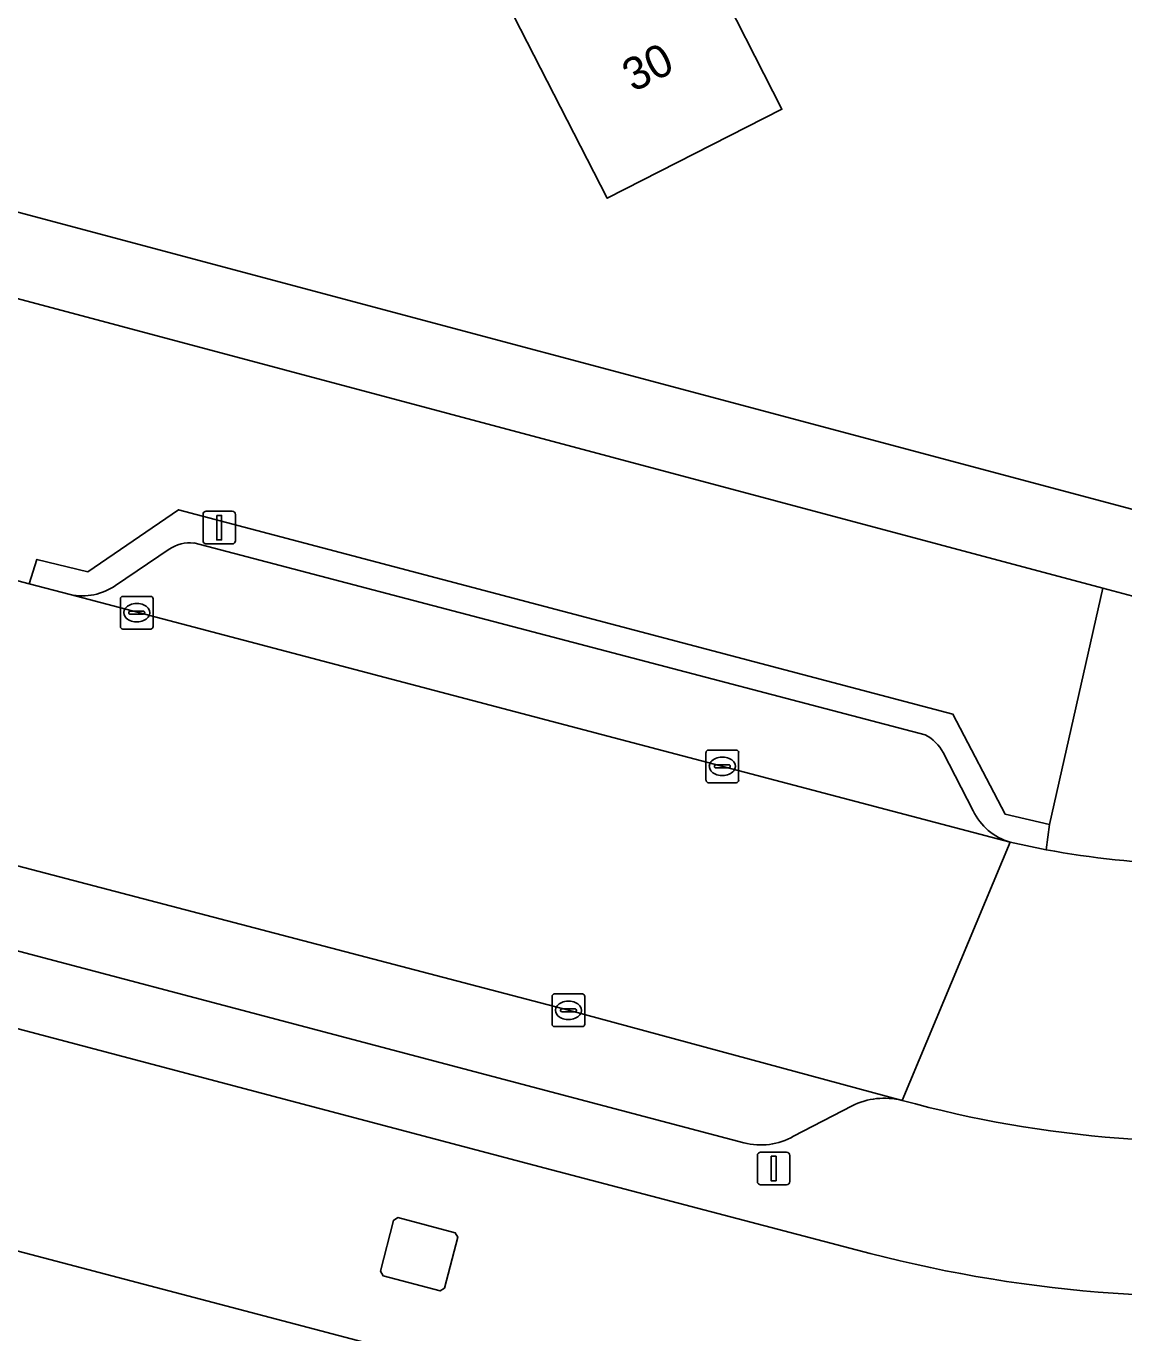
# Model space of a CAD drawing. Extents: x 157692 to 159674, y 381452 to 383291.
# Drawn here: x 158227.96 to 158261.59, y 381802.8 to 381842.84 of the extents above; entities that cross this region are included whole.
import ezdxf

# ---------------------------------------------------------------- set-up
doc = ezdxf.new("R2010")
doc.units = 0
for name, color, linetype in [('IMGEO_Erf', 7, 'Continuous'), ('IMGEO_Groenvoorziening', 7, 'Continuous'), ('IMGEO_Kolk', 7, 'Continuous'), ('IMGEO_Lichtmast', 7, 'Continuous'), ('IMGEO_Pand', 7, 'Continuous'), ('IMGEO_Pand_nummerreeks', 7, 'Continuous'), ('IMGEO_Pand_overbouw', 7, 'Continuous'), ('IMGEO_Parkeervlak_open', 7, 'Continuous'), ('IMGEO_Rijbaan_lokaal_gesloten', 7, 'Continuous'), ('IMGEO_Voetpad_open', 7, 'Continuous')]:
    doc.layers.add(name, color=color, linetype=linetype)

msp = doc.modelspace()

# ---------------------------------------------------------------- linework, layer by layer
at = {"layer": 'IMGEO_Erf'}
for points in [[(158217.316, 381839.906), (158270.263, 381825.792), (158286.558, 381834.286), (158292.839, 381837.605), (158310.343, 381846.755), (158316.773, 381850.116), (158323.795, 381853.778), (158342.759, 381863.76), (158347.941, 381866.531), (158348.596, 381866.872), (158358.563, 381872.057), (158364.635, 381875.26), (158392.478, 381889.849), (158400.12, 381893.872), (158401.991, 381894.865), (158408.14, 381898.064), (158436.465, 381912.9), (158441.823, 381915.706), (158446.378, 381918.092), (158458.186, 381924.156), (158466.161, 381928.413)], [(158253.819, 381805.238), (158243.862, 381807.851), (158213.033, 381815.996)]]:
    msp.add_lwpolyline(points, dxfattribs=at)
for points in [[(158254.852, 381854.574), (158255.418, 381853.453), (158255.111, 381852.605), (158254.751, 381852.415), (158255.581, 381850.766), (158249.983, 381847.89), (158251.049, 381845.761), (158248.895, 381844.653), (158251.116, 381840.294), (158245.765, 381837.569), (158237.787, 381853.137), (158242.24, 381855.413), (158250.92, 381859.848), (158253.579, 381854.659), (158253.979, 381854.851)], [(158239.215, 381806.249), (158239.35, 381806.336), (158241.107, 381805.868), (158241.185, 381805.732), (158240.78, 381804.172), (158240.643, 381804.087), (158238.896, 381804.545), (158238.815, 381804.694)]]:
    msp.add_lwpolyline(points, close=True, dxfattribs=at)
msp.add_arc((158264.149, 381844.935), 41.019, 255.414, 297.495, dxfattribs=at)
at = {"layer": 'IMGEO_Groenvoorziening'}
msp.add_lwpolyline([(158215.806, 381837.663), (158207.529, 381840.178), (158205.116, 381832.151), (158211.577, 381830.197), (158221.36, 381827.534), (158228.057, 381825.755), (158228.292, 381826.502), (158229.853, 381826.117), (158232.631, 381828.023), (158256.357, 381821.757), (158257.958, 381818.699), (158259.317, 381818.381), (158260.949, 381825.619)], close=True, dxfattribs=at)
msp.add_lwpolyline([(158267.734, 381817.384), (158267.631, 381818.175), (158269.03, 381818.388), (158271.535, 381821.61), (158272.252, 381821.977), (158288.606, 381830.362), (158287.729, 381832.027), (158271.462, 381823.491), (158270.606, 381823.042), (158260.949, 381825.619), (158259.317, 381818.381), (158259.211, 381817.606)], dxfattribs=at)
msp.add_arc((158264.168, 381844.191), 27.043, 259.4383, 277.5776, dxfattribs=at)
at = {"layer": 'IMGEO_Kolk'}
for p, q in [((158230.926, 381825.368), (158231.778, 381825.368)), ((158230.851, 381824.442), (158230.851, 381825.294)), ((158231.339, 381825.148), (158231.364, 381825.148)), ((158231.852, 381825.294), (158231.852, 381824.442)), ((158231.11, 381824.862), (158231.11, 381824.874)), ((158231.548, 381824.825), (158231.15, 381824.825)), ((158231.153, 381824.911), (158231.551, 381824.911)), ((158231.362, 381824.588), (158231.337, 381824.588)), ((158231.594, 381824.874), (158231.594, 381824.862)), ((158231.778, 381824.368), (158230.926, 381824.368)), ((158248.792, 381819.734), (158248.792, 381820.586)), ((158248.867, 381820.66), (158249.719, 381820.66)), ((158249.793, 381820.586), (158249.793, 381819.734)), ((158249.051, 381820.154), (158249.051, 381820.166)), ((158249.094, 381820.203), (158249.492, 381820.203)), ((158249.28, 381820.44), (158249.305, 381820.44)), ((158249.535, 381820.166), (158249.535, 381820.154)), ((158249.489, 381820.117), (158249.091, 381820.117)), ((158249.303, 381819.88), (158249.278, 381819.88)), ((158249.719, 381819.66), (158248.867, 381819.66)), ((158244.077, 381812.259), (158244.077, 381813.111)), ((158244.152, 381813.185), (158245.004, 381813.185)), ((158244.565, 381812.965), (158244.59, 381812.965)), ((158245.078, 381813.111), (158245.078, 381812.259)), ((158244.336, 381812.679), (158244.336, 381812.691)), ((158244.774, 381812.642), (158244.376, 381812.642)), ((158244.379, 381812.728), (158244.777, 381812.728)), ((158244.82, 381812.691), (158244.82, 381812.679)), ((158245.004, 381812.185), (158244.152, 381812.185)), ((158244.588, 381812.405), (158244.563, 381812.405))]:
    msp.add_line(p, q, dxfattribs=at)
for points in [[(158230.926, 381825.368), (158231.778, 381825.368)], [(158230.851, 381824.442), (158230.851, 381825.294)], [(158231.852, 381825.294), (158231.852, 381824.442)], [(158231.778, 381824.368), (158230.926, 381824.368)], [(158248.792, 381819.734), (158248.792, 381820.586)], [(158248.867, 381820.66), (158249.719, 381820.66)], [(158249.793, 381820.586), (158249.793, 381819.734)], [(158249.719, 381819.66), (158248.867, 381819.66)], [(158244.077, 381812.259), (158244.077, 381813.111)], [(158244.152, 381813.185), (158245.004, 381813.185)], [(158245.078, 381813.111), (158245.078, 381812.259)], [(158245.004, 381812.185), (158244.152, 381812.185)]]:
    msp.add_lwpolyline(points, dxfattribs=at)
for centre, radius, start, end in [((158230.928, 381825.292), 0.0765, 91.552, 178.448), ((158230.928, 381825.292), 0.0765, 91.552, 178.448), ((158231.776, 381825.292), 0.0765, 1.552, 88.448), ((158231.776, 381825.292), 0.0765, 1.552, 88.448), ((158231.15, 381824.871), 0.0403, 85.8775, 175.7526), ((158231.147, 381824.861), 0.0366, 178.938, 274.7102), ((158231.551, 381824.868), 0.043, 264.8664, 352.4533), ((158231.555, 381824.873), 0.0386, 1.7309, 96.639), ((158230.928, 381824.444), 0.0765, 181.552, 268.448), ((158230.928, 381824.444), 0.0765, 181.552, 268.448), ((158231.776, 381824.444), 0.0765, 271.552, 358.448), ((158231.776, 381824.444), 0.0765, 271.552, 358.448), ((158248.869, 381820.584), 0.0765, 91.552, 178.448), ((158248.869, 381820.584), 0.0765, 91.552, 178.448), ((158249.717, 381820.584), 0.0765, 1.552, 88.448), ((158249.717, 381820.584), 0.0765, 1.552, 88.448), ((158249.091, 381820.163), 0.0403, 85.8775, 175.7526), ((158249.088, 381820.153), 0.0366, 178.938, 274.7102), ((158249.492, 381820.16), 0.043, 264.8664, 352.4533), ((158249.496, 381820.165), 0.0386, 1.7309, 96.639), ((158248.869, 381819.736), 0.0765, 181.552, 268.448), ((158248.869, 381819.736), 0.0765, 181.552, 268.448), ((158249.717, 381819.736), 0.0765, 271.552, 358.448), ((158249.717, 381819.736), 0.0765, 271.552, 358.448), ((158244.154, 381813.109), 0.0765, 91.552, 178.448), ((158244.154, 381813.109), 0.0765, 91.552, 178.448), ((158245.002, 381813.109), 0.0765, 1.552, 88.448), ((158245.002, 381813.109), 0.0765, 1.552, 88.448), ((158244.376, 381812.688), 0.0403, 85.8775, 175.7526), ((158244.373, 381812.678), 0.0366, 178.938, 274.7102), ((158244.777, 381812.685), 0.043, 264.8664, 352.4533), ((158244.781, 381812.69), 0.0386, 1.7309, 96.639), ((158244.154, 381812.261), 0.0765, 181.552, 268.448), ((158244.154, 381812.261), 0.0765, 181.552, 268.448), ((158245.002, 381812.261), 0.0765, 271.552, 358.448), ((158245.002, 381812.261), 0.0765, 271.552, 358.448)]:
    msp.add_arc(centre, radius, start, end, dxfattribs=at)
for centre, major_axis, ratio, start_param, end_param in [((158231.338, 381824.868), (-0.387, 0.002), 0.722429, 4.712389, 7.853982), ((158231.363, 381824.868), (-0.39, 0.002), 0.717154, 1.570796, 4.712389), ((158249.279, 381820.16), (-0.387, 0.002), 0.722429, 4.712389, 7.853982), ((158249.304, 381820.16), (-0.39, 0.002), 0.717154, 1.570796, 4.712389), ((158244.564, 381812.685), (-0.387, 0.002), 0.722429, 4.712389, 7.853982), ((158244.589, 381812.685), (-0.39, 0.002), 0.717154, 1.570796, 4.712389)]:
    msp.add_ellipse(centre, major_axis=major_axis, ratio=ratio, start_param=start_param, end_param=end_param, dxfattribs=at)
at = {"layer": 'IMGEO_Lichtmast'}
for p, q in [((158233.382, 381827.075), (158233.382, 381827.875)), ((158233.382, 381827.875), (158233.382, 381827.075)), ((158233.482, 381827.975), (158234.272, 381827.975)), ((158234.272, 381827.975), (158233.482, 381827.975)), ((158234.372, 381827.875), (158234.372, 381827.075)), ((158234.372, 381827.075), (158234.372, 381827.875)), ((158234.272, 381826.975), (158233.482, 381826.975)), ((158233.482, 381826.975), (158234.272, 381826.975)), ((158250.367, 381807.439), (158250.367, 381808.239)), ((158250.367, 381808.239), (158250.367, 381807.439)), ((158250.467, 381808.339), (158251.257, 381808.339)), ((158251.257, 381808.339), (158250.467, 381808.339)), ((158251.357, 381808.239), (158251.357, 381807.439)), ((158251.357, 381807.439), (158251.357, 381808.239)), ((158251.257, 381807.339), (158250.467, 381807.339)), ((158250.467, 381807.339), (158251.257, 381807.339))]:
    msp.add_line(p, q, dxfattribs=at)
for points in [[(158233.802, 381827.85), (158233.952, 381827.85), (158233.952, 381827.1), (158233.802, 381827.1), (158233.802, 381827.85)], [(158250.787, 381808.214), (158250.937, 381808.214), (158250.937, 381807.464), (158250.787, 381807.464), (158250.787, 381808.214)]]:
    msp.add_lwpolyline(points, dxfattribs=at)
for centre, start, end in [((158233.482, 381827.875), 90, 180), ((158233.482, 381827.875), 90, 180), ((158234.272, 381827.875), 0, 90), ((158234.272, 381827.875), 360, 90), ((158233.482, 381827.075), 180, 270), ((158233.482, 381827.075), 180, 270), ((158234.272, 381827.075), 270, 0), ((158234.272, 381827.075), 270, 0), ((158250.467, 381808.239), 90, 180), ((158250.467, 381808.239), 90, 180), ((158251.257, 381808.239), 0, 90), ((158251.257, 381808.239), 360, 90), ((158250.467, 381807.439), 180, 270), ((158250.467, 381807.439), 180, 270), ((158251.257, 381807.439), 270, 0), ((158251.257, 381807.439), 270, 0)]:
    msp.add_arc(centre, 0.1, start, end, dxfattribs=at)
at = {"layer": 'IMGEO_Pand'}
for points in [[(158254.852, 381854.574), (158253.979, 381854.851), (158253.579, 381854.659), (158250.92, 381859.848), (158242.24, 381855.413), (158237.787, 381853.137), (158245.765, 381837.569), (158251.116, 381840.294), (158248.895, 381844.653), (158251.049, 381845.761), (158249.983, 381847.89), (158255.581, 381850.766), (158254.751, 381852.415), (158255.111, 381852.605), (158255.418, 381853.453)], [(158240.643, 381804.087), (158240.78, 381804.172), (158241.185, 381805.732), (158241.107, 381805.868), (158239.35, 381806.336), (158239.215, 381806.249), (158238.815, 381804.694), (158238.896, 381804.545)]]:
    msp.add_lwpolyline(points, close=True, dxfattribs=at)
at = {"layer": 'IMGEO_Pand_overbouw'}
msp.add_lwpolyline([(158212.268, 381809.365), (158211.103, 381804.95), (158239.469, 381797.491), (158240.637, 381801.905)], close=True, dxfattribs=at)
at = {"layer": 'IMGEO_Parkeervlak_open'}
for points in [[(158255.511, 381821.123), (158233.1, 381827.004)], [(158232.348, 381826.814), (158230.701, 381825.705)], [(158229.313, 381825.422), (158258.116, 381817.836)], [(158254.798, 381809.926), (158244.579, 381812.686), (158225.974, 381817.565), (158207.066, 381822.725)], [(158256.977, 381818.801), (158256.062, 381820.587)], [(158213.614, 381818.224), (158249.956, 381808.626)], [(158251.477, 381808.829), (158253.266, 381809.759)]]:
    msp.add_lwpolyline(points, dxfattribs=at)
for centre, radius, start, end in [((158232.986, 381825.872), 1.137, 84.2451, 124.114), ((158229.685, 381827.145), 1.763, 257.8322, 305.2161), ((158254.878, 381819.921), 1.358, 29.3521, 62.2291), ((158258.613, 381819.577), 1.811, 205.3811, 254.0741), ((158254.259, 381807.762), 2.23, 76.0113, 116.4309), ((158250.468, 381810.588), 2.028, 255.3677, 299.8364)]:
    msp.add_arc(centre, radius, start, end, dxfattribs=at)
at = {"layer": 'IMGEO_Rijbaan_lokaal_gesloten'}
for points in [[(158207.066, 381822.725), (158225.974, 381817.565), (158244.579, 381812.686), (158254.798, 381809.926), (158258.116, 381817.836), (158229.313, 381825.422), (158228.057, 381825.755), (158221.36, 381827.534), (158211.577, 381830.197), (158205.116, 381832.151), (158198.373, 381834.361)], [(158259.211, 381817.606), (158258.116, 381817.836), (158254.798, 381809.926)]]:
    msp.add_lwpolyline(points, dxfattribs=at)
for centre, radius, start, end in [((158264.168, 381844.191), 27.043, 259.4383, 277.5776), ((158264.153, 381843.952), 35.289, 254.6277, 298.2751)]:
    msp.add_arc(centre, radius, start, end, dxfattribs=at)
at = {"layer": 'IMGEO_Voetpad_open'}
msp.add_lwpolyline([(158271.462, 381823.491), (158287.729, 381832.027), (158286.558, 381834.286), (158270.263, 381825.792), (158217.316, 381839.906), (158208.31, 381842.627), (158207.529, 381840.178), (158215.806, 381837.663), (158260.949, 381825.619), (158270.606, 381823.042)], close=True, dxfattribs=at)
for points in [[(158258.116, 381817.836), (158259.211, 381817.606), (158259.317, 381818.381), (158257.958, 381818.699), (158256.357, 381821.757), (158232.631, 381828.023), (158229.853, 381826.117), (158228.292, 381826.502), (158228.057, 381825.755), (158229.313, 381825.422)], [(158233.1, 381827.004), (158255.511, 381821.123)], [(158230.701, 381825.705), (158232.348, 381826.814)], [(158256.062, 381820.587), (158256.977, 381818.801)], [(158249.956, 381808.626), (158213.614, 381818.224), (158213.033, 381815.996), (158243.862, 381807.851), (158253.819, 381805.238)], [(158253.266, 381809.759), (158251.477, 381808.829)]]:
    msp.add_lwpolyline(points, dxfattribs=at)
for centre, radius, start, end in [((158232.986, 381825.872), 1.137, 84.2451, 124.114), ((158229.685, 381827.145), 1.763, 257.8322, 305.2161), ((158254.878, 381819.921), 1.358, 29.3521, 62.2291), ((158258.613, 381819.577), 1.811, 205.3811, 254.0741), ((158264.153, 381843.952), 35.289, 254.6277, 298.2751), ((158254.259, 381807.762), 2.23, 76.0113, 116.4309), ((158250.468, 381810.588), 2.028, 255.3677, 299.8364), ((158264.149, 381844.935), 41.019, 255.414, 297.495)]:
    msp.add_arc(centre, radius, start, end, dxfattribs=at)

# ---------------------------------------------------------------- texts
at = {"layer": 'IMGEO_Pand_nummerreeks'}
msp.add_text('30', height=1, rotation=26.9875, dxfattribs=at).set_placement((158246.563, 381840.804))

doc.saveas('drawing.dxf')
